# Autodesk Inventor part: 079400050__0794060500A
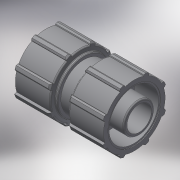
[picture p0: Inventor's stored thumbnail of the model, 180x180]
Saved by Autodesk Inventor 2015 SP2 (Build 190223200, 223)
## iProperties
Created: 2017-04
Part Number: 079400050__0794060500A
Material: Generic
Description: PLASSON MODULAR ADAPTOR 50
Document SubType Name: Modeling
Designer: KIM
Mass: 332 g
Surface Area: 773.229 cm^2
Volume: 332 cm^3
Density: 1 g/cm^3
Appearance: Default
Author: KIM
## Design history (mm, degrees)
derived "07940.ipt"
feature "Solid1::07940.ipt"
tag "TaggingFeature1"
body "Solid1"
other parameters: "d7" = 93, "d8" = 74.4, "d15" = 69.75, "d17" = 42.8, "d43" = 100 deg, "d46" = 86.49, "d47" = 35 deg, "d48" = 17.5 deg, "d50" = 0, "d52" = 360 deg, "d54" = 1.86, "d57" = 1.86, "d68" = 38.52, "d69" = 0.5, "d70" = 3.852, "d71" = 5, "d73" = 53.5, "d74" = 48.15, "d75" = 65.1, "d76" = 0.93, "d77" = 1.86, "d79" = 360 deg, "d81" = 1.86, "d82" = 21.4, "E_" = 93, "H_" = 107
